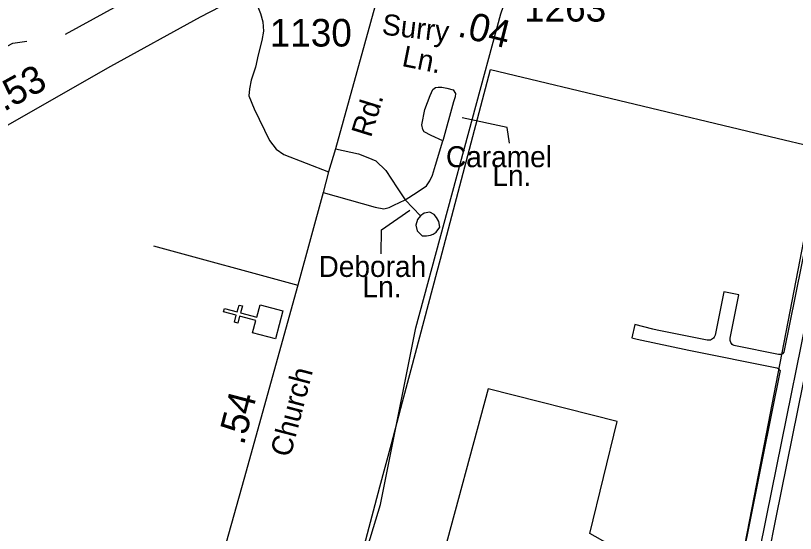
# Model space of a CAD drawing. Extents: x 2206922 to 2357709, y 510027 to 673830.
# Drawn here: x 2284540 to 2288072, y 577189 to 579534 of the extents above; entities that cross this region are included whole.
import ezdxf

# ---------------------------------------------------------------- set-up
doc = ezdxf.new("R2010")
doc.units = 0
for name, color, linetype in [('Exist Boundary Political City Limit New', 7, 'Continuous'), ('Exist Boundary Political Urban Extension UEB', 7, 'Continuous'), ('Exist Cultural Church CELL', 7, 'Continuous'), ('Exist Hydrographic Misc Water Feature', 7, 'Continuous'), ('Exist Road Non-System Type 51', 7, 'Continuous'), ('Exist Road Non-System Type 51 Label', 7, 'Continuous'), ('Exist Road Primary US Divided Attributed', 7, 'Continuous'), ('Exist Road Secondary Mileage Hundredths English Label', 7, 'Continuous'), ('Exist Road Secondary Type 51 Attributed', 7, 'Continuous'), ('Exist Road Secondary Type 51 Label', 7, 'Continuous'), ('Exist Road Secondary Type 51 Number Label', 7, 'Continuous'), ('Map Preparation Boundary City Limit Buffer Line', 7, 'Continuous')]:
    doc.layers.add(name, color=color, linetype=linetype)

msp = doc.modelspace()

# ---------------------------------------------------------------- linework, layer by layer
at = {"layer": 'Exist Boundary Political City Limit New'}
for points in [[(2286112.8, 577108.6), (2286189.8, 577398.9), (2286241.8, 577594.8), (2286292.5, 577785.2), (2286331.2, 577931.2), (2286449, 578374.8), (2286463.8, 578430.3), (2286690.2, 579289.2), (2287926.2, 578994.3), (2288204.5, 578927.9), (2288019.5, 578010)], [(2288019.5, 578010), (2288013.8, 578002.4), (2288008.2, 577999.2), (2287995.8, 577998.4), (2287799.8, 578037.8), (2287794.8, 578039.3), (2287790, 578041.6), (2287785.8, 578044.8), (2287782.2, 578048.5), (2287779.2, 578052.9), (2287777.2, 578057.7), (2287776, 578062.8), (2287775.8, 578068), (2287776.2, 578073.2), (2287815.8, 578269.2), (2287747, 578283.1), (2287707.8, 578087), (2287703.8, 578077.2), (2287700.8, 578073.1), (2287692.5, 578066.6), (2287687.8, 578064.4), (2287672.2, 578063.4), (2287445.2, 578109.1), (2287425.8, 578113.7), (2287345.2, 578135.2), (2287331, 578074.1), (2287355.2, 578068.9), (2287589.2, 578018.2), (2287987.8, 577938.2), (2287993, 577934.8), (2288002.8, 577926.4)], [(2288002.8, 577926.4), (2287922.8, 577529.7), (2287869.2, 577264.8), (2287830, 577070.2)], [(2287307.5, 577094), (2287140, 577188.9), (2287264, 577695.9), (2286679.5, 577843.3), (2286242.5, 576225.4)]]:
    msp.add_lwpolyline(points, dxfattribs=at)
at = {"layer": 'Exist Boundary Political Urban Extension UEB'}
msp.add_line((2287895.1, 577405.1), (2288177.3, 578865.9), dxfattribs=at)
msp.add_lwpolyline([(2287800.8, 576929.9), (2287833.6, 577086.7), (2287895.1, 577405.1)], dxfattribs=at)
at = {"layer": 'Exist Cultural Church CELL'}
msp.add_lwpolyline([(2285613.3, 578097.7), (2285628, 578152.7), (2285554.5, 578172.5), (2285546.2, 578141.6), (2285530.8, 578145.8), (2285539.1, 578176.7), (2285481, 578192.4), (2285485.2, 578207.8), (2285543.3, 578192.2), (2285551.6, 578223.1), (2285567, 578218.9), (2285558.7, 578188), (2285632.2, 578168.1), (2285647.3, 578223.8), (2285750.1, 578196), (2285716.1, 578069.9)], close=True, dxfattribs=at)
at = {"layer": 'Exist Hydrographic Misc Water Feature'}
for points in [[(2284538.8, 575198.7), (2284783.8, 575692.2), (2284977.8, 576285.2), (2285067.8, 576470.3), (2285216.9, 576536.1), (2285873.9, 576683.6), (2285981.7, 576753.5), (2286046.7, 576837.4), (2286192.7, 577319.9), (2286351.8, 578120.2), (2286737.8, 579542.2), (2286883.8, 579965.6), (2286998.8, 580117.4), (2287239.9, 580253.5), (2287662.7, 580356.5), (2288270.9, 580422.9), (2288778.8, 580409.4), (2289170.9, 580355.5), (2289596.8, 580199.3), (2289871.8, 580210.1), (2289954.8, 580238), (2290283.9, 580615), (2290491.9, 580699.3)], [(2284765.2, 579449.2), (2285065.4, 579616.1)]]:
    msp.add_lwpolyline(points, dxfattribs=at)
at = {"layer": 'Exist Road Non-System Type 51'}
for p, q in [((2286304.2, 578700.1), (2286373.9, 578626.9)), ((2285164.2, 578491.4), (2285818.1, 578313.3))]:
    msp.add_line(p, q, dxfattribs=at)
for points in [[(2285604.4, 579648.1), (2285631.2, 579589.3), (2285649, 579543.4), (2285659.3, 579506.3), (2285661.8, 579462.9), (2285654.2, 579420.8), (2285638.8, 579355.7), (2285626.1, 579300.8), (2285606.9, 579240.8), (2285599.3, 579202.5), (2285595.5, 579170.6), (2285619.7, 579111.9), (2285689.9, 578967.6), (2285719.2, 578929.3), (2285755, 578905), (2285956.6, 578825.9)], [(2284285.9, 578871.8), (2284240.7, 578913.4), (2284204.6, 578964), (2284154, 579027.2), (2284128.7, 579090.4), (2284119.7, 579159.1), (2284125.1, 579195.2), (2284144.1, 579216), (2284187.4, 579235.9), (2284221.8, 579254), (2284290.4, 579277.5), (2284342.7, 579299.1), (2284409.6, 579347.9), (2284526.9, 579409.4), (2284590.2, 579418.4)], [(2286474.5, 578967), (2286422.4, 578991), (2286389.9, 579007.9), (2286384.3, 579017.8), (2286380.1, 579038.9), (2286392.8, 579109.4), (2286418.1, 579171.5), (2286430.1, 579199.7), (2286442.1, 579208.1), (2286453.3, 579209.9), (2286470.9, 579210.4), (2286492.4, 579205.7), (2286521, 579198.2), (2286532.3, 579181.3), (2286531.2, 579165.8), (2286523.8, 579143.3), (2286474.5, 578967)], [(2286304.2, 578700.1), (2286358.9, 578734.8), (2286400.7, 578763.1), (2286415.9, 578785), (2286427.4, 578810.6), (2286441.4, 578856.5), (2286474.5, 578967)], [(2285988.4, 578930.6), (2286092.3, 578907.3), (2286134.9, 578891.6), (2286171.9, 578876), (2286216.2, 578832.9), (2286267.2, 578753.8), (2286304.2, 578700.1)], [(2285932.9, 578732.1), (2286169, 578665.7), (2286207.3, 578659.3), (2286231.5, 578664.4), (2286253.2, 578675.9), (2286304.2, 578700.1)], [(2286373.9, 578626.9), (2286360, 578610.8), (2286352.3, 578584.8), (2286358.5, 578558.9), (2286380.7, 578537), (2286400.7, 578537.2), (2286418.7, 578539.5), (2286430.6, 578543.6), (2286444.6, 578553.7), (2286460.5, 578575.8), (2286456.2, 578601.7), (2286445.9, 578619.7), (2286435.8, 578633.5), (2286415.8, 578643.3), (2286389.8, 578639), (2286373.9, 578626.9)]]:
    msp.add_lwpolyline(points, dxfattribs=at)
at = {"layer": 'Exist Road Non-System Type 51 Label'}
for points in [[(2286777.3, 578956.4), (2286766.7, 579026.8), (2286562, 579071.6)], [(2286195.3, 578455), (2286197.5, 578563.8), (2286325.4, 578653.4)]]:
    msp.add_lwpolyline(points, dxfattribs=at)
at = {"layer": 'Exist Road Primary US Divided Attributed'}
for points in [[(2288672.5, 580293.8), (2288641.2, 580235.2), (2288604.1, 580161), (2288567, 580068.1), (2288521.5, 579960.1), (2288482.7, 579852.1), (2288440.5, 579722.2), (2288401.7, 579570.3), (2288341.1, 579268.2), (2288186.3, 578484.2), (2287941.4, 577270.2), (2287870.4, 576918.4)], [(2287914.5, 576909.9), (2287985.4, 577261.3), (2288230.3, 578475.4), (2288385.1, 579259), (2288449.7, 579552.7), (2288490.3, 579709.4), (2288530.8, 579833.8), (2288575.4, 579939.9), (2288624.4, 580058), (2288661.5, 580145.8), (2288688.5, 580198.1), (2288718.1, 580251.5)]]:
    msp.add_lwpolyline(points, dxfattribs=at)
at = {"layer": 'Exist Road Secondary Type 51 Attributed'}
for points in [[(2283881.3, 578436.3), (2283951.8, 578526.7), (2284051.1, 578645.9), (2284192, 578790.5), (2284244.3, 578841.1), (2284285.9, 578871.8), (2284385.2, 578956.7), (2284502.6, 579038), (2284971.2, 579304.6), (2285376.6, 579527.7), (2285604.4, 579648.1), (2285795, 579754.2), (2286184.7, 579967.7)], [(2286182.6, 579628.9), (2285988.4, 578930.6), (2285956.6, 578825.9), (2285932.9, 578732.1), (2285818.1, 578313.3), (2285572.8, 577433.4), (2285299.1, 576452.9)]]:
    msp.add_lwpolyline(points, dxfattribs=at)
at = {"layer": 'Map Preparation Boundary City Limit Buffer Line'}
for points in [[(2286112.8, 577108.6), (2286189.8, 577398.9), (2286241.8, 577594.8), (2286292.5, 577785.2), (2286331.2, 577931.2), (2286449, 578374.8), (2286463.8, 578430.3), (2286690.2, 579289.2), (2287926.2, 578994.3), (2288204.5, 578927.9), (2288019.5, 578010)], [(2288019.5, 578010), (2288013.8, 578002.4), (2288008.2, 577999.2), (2287995.8, 577998.4), (2287799.8, 578037.8), (2287794.8, 578039.3), (2287790, 578041.6), (2287785.8, 578044.8), (2287782.2, 578048.5), (2287779.2, 578052.9), (2287777.2, 578057.7), (2287776, 578062.8), (2287775.8, 578068), (2287776.2, 578073.2), (2287815.8, 578269.2), (2287747, 578283.1), (2287707.8, 578087), (2287703.8, 578077.2), (2287700.8, 578073.1), (2287692.5, 578066.6), (2287687.8, 578064.4), (2287672.2, 578063.4), (2287445.2, 578109.1), (2287425.8, 578113.7), (2287345.2, 578135.2), (2287331, 578074.1), (2287355.2, 578068.9), (2287589.2, 578018.2), (2287987.8, 577938.2), (2287993, 577934.8), (2288002.8, 577926.4)], [(2288002.8, 577926.4), (2287922.8, 577529.7), (2287869.2, 577264.8), (2287830, 577070.2)], [(2287307.5, 577094), (2287140, 577188.9), (2287264, 577695.9), (2286679.5, 577843.3), (2286242.5, 576225.4)]]:
    msp.add_lwpolyline(points, dxfattribs=at)

# ---------------------------------------------------------------- texts
at = {"layer": 'Exist Road Non-System Type 51 Label'}
for s, p in [('Caramel', (2286489, 578847.3)), ('Ln.', (2286699.3, 578762)), ('Deborah', (2285912, 578350.3)), ('Ln.', (2286110.9, 578258.5))]:
    msp.add_text(s, height=95, dxfattribs=at).set_placement(p)
at = {"layer": 'Exist Road Secondary Mileage Hundredths English Label'}
for s, rotation, p in [('.04', 345.945, (2286536.8, 579441.3)), ('.53', 28.6611, (2284486.4, 579097.2)), ('.54', 75.3592, (2285573.3, 577584.8))]:
    msp.add_text(s, height=125, rotation=rotation, dxfattribs=at).set_placement(p)
at = {"layer": 'Exist Road Secondary Type 51 Label'}
for s, rotation, p in [('Surry', 353.286, (2286195.6, 579448.8)), ('Ln.', 348.6834, (2286285.1, 579306.3)), ('Rd.', 72.8277, (2286149, 578978.1)), ('Church', 75.3592, (2285783.8, 577529.8))]:
    msp.add_text(s, height=95, rotation=rotation, dxfattribs=at).set_placement(p)
at = {"layer": 'Exist Road Secondary Type 51 Number Label'}
for s, p in [('1263', (2286842.9, 579506.9)), ('1130', (2285690.7, 579393.8))]:
    msp.add_text(s, height=125, dxfattribs=at).set_placement(p)

doc.saveas('drawing.dxf')
